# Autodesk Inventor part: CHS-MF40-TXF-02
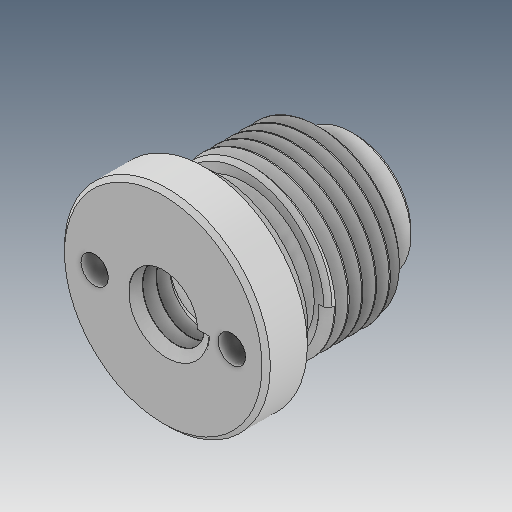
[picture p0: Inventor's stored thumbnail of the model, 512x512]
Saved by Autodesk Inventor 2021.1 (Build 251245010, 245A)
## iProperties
Created: 2019-04
Part Number: CHS-MF40-TXF-02
Material: Ogólny
Document SubType Name: Modeling
Designer: user
Density: 1 g/cm^3
Appearance: Domyślna
Author: user
Revision Number: ÈÎºÎ
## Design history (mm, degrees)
feature "ÊäÈë1"
node "Bryła1"
